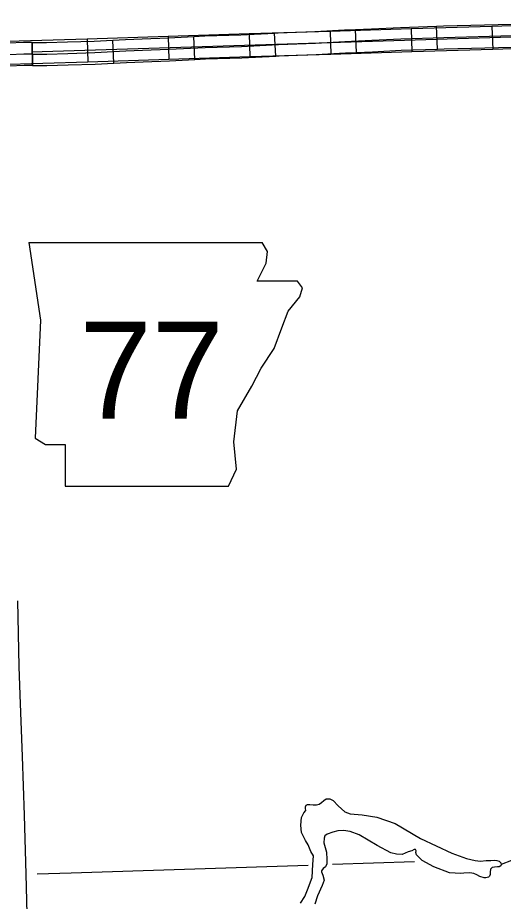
# Model space of a CAD drawing. Extents: x -117616 to 64730, y 54117 to 789866.
# Drawn here: x 63089.6 to 63152.9, y 54954.6 to 55069.9 of the extents above; entities that cross this region are included whole.
import ezdxf

# ---------------------------------------------------------------- set-up
doc = ezdxf.new("R2010")
doc.units = 0
for name, color, linetype in [('10', 7, 'Continuous'), ('21', 7, 'Continuous'), ('32', 7, 'Continuous'), ('35', 7, 'Continuous'), ('45', 7, 'Continuous'), ('6', 7, 'Continuous')]:
    doc.layers.add(name, color=color, linetype=linetype)

msp = doc.modelspace()

# ---------------------------------------------------------------- linework, layer by layer
at = {"layer": '10'}
msp.add_lwpolyline([(63091.8, 54919.42), (63091.76, 54920.65), (63091.56, 54926.73), (63091.46, 54930.57), (63091.28, 54937.35), (63091.13, 54943.67), (63090.88, 54951.22), (63090.72, 54958.12), (63090.51, 54965.85), (63090.23, 54973.47), (63089.94, 54981.52), (63089.82, 54985.23), (63089.61, 54993.8)], dxfattribs=at)
at = {"layer": '21'}
for p, q in [((63091.05, 55040.58), (63092.58, 55030.43)), ((63122.18, 55039.39), (63121.48, 55040.56)), ((63122.01, 55037.87), (63122.18, 55039.39)), ((63120.83, 55035.5), (63122.01, 55037.87)), ((63126.08, 55035.5), (63120.83, 55035.5)), ((63126.75, 55034.66), (63126.08, 55035.5)), ((63126.41, 55033.47), (63126.75, 55034.66)), ((63124.89, 55031.61), (63126.41, 55033.47)), ((63124.04, 55029.41), (63124.89, 55031.61)), ((63092.58, 55030.43), (63091.9, 55015.03)), ((63123.03, 55026.71), (63124.04, 55029.41)), ((63121.34, 55024.17), (63123.03, 55026.71)), ((63120.15, 55021.8), (63121.34, 55024.17)), ((63118.29, 55018.59), (63120.15, 55021.8)), ((63117.79, 55014.53), (63118.29, 55018.59)), ((63091.9, 55015.03), (63093.25, 55014.19)), ((63093.25, 55014.19), (63095.79, 55014.19)), ((63095.79, 55014.19), (63095.79, 55008.77)), ((63118.12, 55010.97), (63117.79, 55014.53)), ((63117.11, 55008.77), (63118.12, 55010.97)), ((63095.79, 55008.77), (63117.11, 55008.77))]:
    msp.add_line(p, q, dxfattribs=at)
msp.add_lwpolyline([(63091.05, 55040.58), (63121.48, 55040.56)], dxfattribs=at)
at = {"layer": '32'}
for p, q in [((63130.33, 55068.1), (63130.43, 55065.1)), ((63133.8, 55065.36), (63133.66, 55068.36)), ((63140.89, 55068.43), (63140.98, 55065.43)), ((63144.33, 55065.8), (63144.23, 55068.79)), ((63151.44, 55068.76), (63151.54, 55065.76)), ((63098.67, 55067.11), (63098.76, 55064.11)), ((63102.16, 55063.97), (63102.01, 55066.96)), ((63109.22, 55067.44), (63109.32, 55064.44)), ((63112.7, 55064.44), (63112.56, 55067.44)), ((63119.78, 55067.77), (63119.87, 55064.77)), ((63123.26, 55064.89), (63123.1, 55067.88)), ((63091.53, 55063.64), (63091.52, 55066.64))]:
    msp.add_line(p, q, dxfattribs=at)
for points in [[(63235.93, 55069.9), (63091.4, 55065.38)], [(63235.93, 55069.9), (63091.4, 55065.38)], [(63235.93, 55069.9), (63091.4, 55065.38)], [(63130.33, 55068.1), (63119.78, 55067.77)], [(63123.1, 55067.88), (63123.55, 55067.91), (63128.37, 55068.09), (63132.21, 55068.29), (63133.66, 55068.36)], [(63140.89, 55068.43), (63130.33, 55068.1)], [(63133.66, 55068.36), (63135.72, 55068.45), (63139.5, 55068.63), (63144.23, 55068.79)], [(63151.44, 55068.76), (63140.89, 55068.43)], [(63144.23, 55068.79), (63145.11, 55068.82), (63154.02, 55069.07), (63154.79, 55069.09)], [(63162, 55069.09), (63151.44, 55068.76)], [(63098.67, 55067.11), (63086.8, 55066.74)], [(63091.52, 55066.64), (63093.37, 55066.65), (63096.11, 55066.73), (63099.6, 55066.84), (63102.01, 55066.96)], [(63091.53, 55065.14), (63093.39, 55065.15), (63096.15, 55065.23), (63099.67, 55065.34), (63103.72, 55065.55), (63105.88, 55065.64), (63109.33, 55065.78), (63114.05, 55066.01), (63118.77, 55066.15), (63123.62, 55066.41), (63128.44, 55066.59), (63132.28, 55066.79), (63135.79, 55066.96), (63139.56, 55067.13), (63145.15, 55067.33), (63154.06, 55067.57)], [(63109.22, 55067.44), (63098.67, 55067.11)], [(63102.01, 55066.96), (63103.65, 55067.05), (63105.82, 55067.14), (63109.26, 55067.28), (63112.56, 55067.44)], [(63119.78, 55067.77), (63109.22, 55067.44)], [(63112.56, 55067.44), (63114, 55067.51), (63118.71, 55067.65), (63123.1, 55067.88)], [(63133.8, 55065.36), (63135.86, 55065.46), (63139.62, 55065.64), (63144.33, 55065.8)], [(63151.54, 55065.76), (63140.98, 55065.43)], [(63144.33, 55065.8), (63145.2, 55065.83), (63154.1, 55066.07), (63154.88, 55066.09)], [(63162.09, 55066.09), (63151.54, 55065.76)], [(63119.87, 55064.77), (63109.32, 55064.44)], [(63112.7, 55064.44), (63114.11, 55064.51), (63118.83, 55064.65), (63123.26, 55064.89)], [(63130.43, 55065.1), (63119.87, 55064.77)], [(63123.26, 55064.89), (63123.69, 55064.91), (63128.51, 55065.09), (63132.36, 55065.29), (63133.8, 55065.36)], [(63140.98, 55065.43), (63130.43, 55065.1)], [(63098.76, 55064.11), (63086.96, 55063.74)], [(63091.53, 55063.64), (63093.42, 55063.65), (63096.2, 55063.73), (63099.73, 55063.84), (63102.16, 55063.97)], [(63109.32, 55064.44), (63098.76, 55064.11)], [(63102.16, 55063.97), (63103.8, 55064.05), (63105.95, 55064.14), (63109.39, 55064.28), (63112.7, 55064.44)]]:
    msp.add_lwpolyline(points, dxfattribs=at)
at = {"layer": '35'}
for points in [[(63127.99, 54957.69), (63128.11, 54959.41), (63128.17, 54960.53), (63127.85, 54961.1), (63127.48, 54961.96), (63127.14, 54962.53), (63126.61, 54963.57), (63126.52, 54964.52), (63126.63, 54965.52), (63126.91, 54966.16), (63127.16, 54966.46), (63127.14, 54966.71), (63127.14, 54966.91), (63127.24, 54967.13), (63127.38, 54967.24), (63127.69, 54967.24), (63128.15, 54967.17), (63128.56, 54967.17), (63128.91, 54967.28), (63129.23, 54967.48), (63129.52, 54967.77), (63129.84, 54967.95), (63130.29, 54967.95), (63130.74, 54967.75), (63131.39, 54967.05), (63132.27, 54966.26), (63132.96, 54965.99), (63134.53, 54965.89), (63136.42, 54965.56), (63138.83, 54964.73), (63142.15, 54962.79), (63146.22, 54960.88)], [(63146.22, 54960.88), (63148.14, 54960.16), (63149.24, 54959.94), (63149.95, 54959.82), (63150.7, 54959.92), (63151.31, 54959.94), (63151.8, 54959.96), (63152.07, 54959.94), (63152.37, 54959.84), (63152.6, 54959.61), (63152.66, 54959.37), (63152.6, 54959.22), (63152.39, 54959.1), (63152.15, 54959.08), (63151.76, 54959.04), (63151.46, 54959.02), (63151.27, 54958.78), (63151.23, 54958.39), (63151.23, 54958.08), (63151.13, 54957.86), (63150.99, 54957.76), (63150.66, 54957.67), (63150.42, 54957.67), (63149.87, 54957.82), (63149.48, 54958.06), (63149.09, 54958.22), (63148.54, 54958.29), (63147.79, 54958.25), (63147.4, 54958.22), (63145.92, 54958.31), (63143.88, 54959.08), (63142.35, 54959.92), (63141.62, 54960.65), (63141.54, 54960.98), (63141.56, 54961.2), (63141.48, 54961.34), (63141.31, 54961.34), (63140.99, 54961.18), (63140.52, 54961.04), (63139.74, 54960.71), (63139.01, 54960.73), (63138.26, 54960.92), (63136.49, 54961.89), (63134.14, 54963.26), (63132.98, 54963.71), (63132.09, 54963.83), (63131.33, 54963.79), (63130.68, 54963.61), (63129.97, 54963.36), (63129.64, 54963.14), (63129.56, 54962.85), (63129.54, 54962.22), (63129.89, 54961), (63129.93, 54960.06), (63129.93, 54959.49), (63129.74, 54959.1), (63129.46, 54958.88), (63129.23, 54958.57), (63129.23, 54958.43), (63129.32, 54958.22), (63129.38, 54958.02), (63129.56, 54957.35), (63129.32, 54956.68), (63128.68, 54955.33), (63128.34, 54954.21)], [(63160.67, 54963.2), (63159.73, 54962.04), (63159.08, 54961.69), (63157.85, 54961.26), (63155.39, 54960.61), (63153.98, 54959.94), (63152.64, 54959.39)], [(63126.48, 54954.37), (63127.03, 54955.23), (63127.4, 54956.1), (63127.99, 54957.69)]]:
    msp.add_lwpolyline(points, dxfattribs=at)
at = {"layer": '45'}
msp.add_line((63091.52, 55066.64), (63091.53, 55063.64), dxfattribs=at)
for points in [[(63091.52, 55066.64), (63090.39, 55066.64), (63088.4, 55066.55), (63087.13, 55066.5)], [(63091.53, 55065.14), (63090.43, 55065.14), (63088.46, 55065.06), (63086.45, 55064.97), (63085.85, 55064.91), (63084.71, 55064.86)], [(63091.53, 55063.64), (63090.46, 55063.64), (63088.52, 55063.56), (63087.25, 55063.5)]]:
    msp.add_lwpolyline(points, dxfattribs=at)
at = {"layer": '6'}
for points in [[(63141.36, 54959.74), (63130.67, 54959.39)], [(63127.48, 54959.28), (63096.6, 54958.27), (63092.13, 54958.15)]]:
    msp.add_lwpolyline(points, dxfattribs=at)

# ---------------------------------------------------------------- texts
at = {"layer": '21'}
msp.add_text('77', height=12.672, dxfattribs=at).set_placement((63097.66, 55017.57))

doc.saveas('drawing.dxf')
